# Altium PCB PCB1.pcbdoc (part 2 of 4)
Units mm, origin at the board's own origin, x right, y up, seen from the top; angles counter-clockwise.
Board outline 96.27 x 122.17 mm, 6 copper layers (Top Layer, Inner1, Inner2, Inner3, Inner4, Bottom Layer); 169 components, 166 nets, 787 pads, 477 vias.
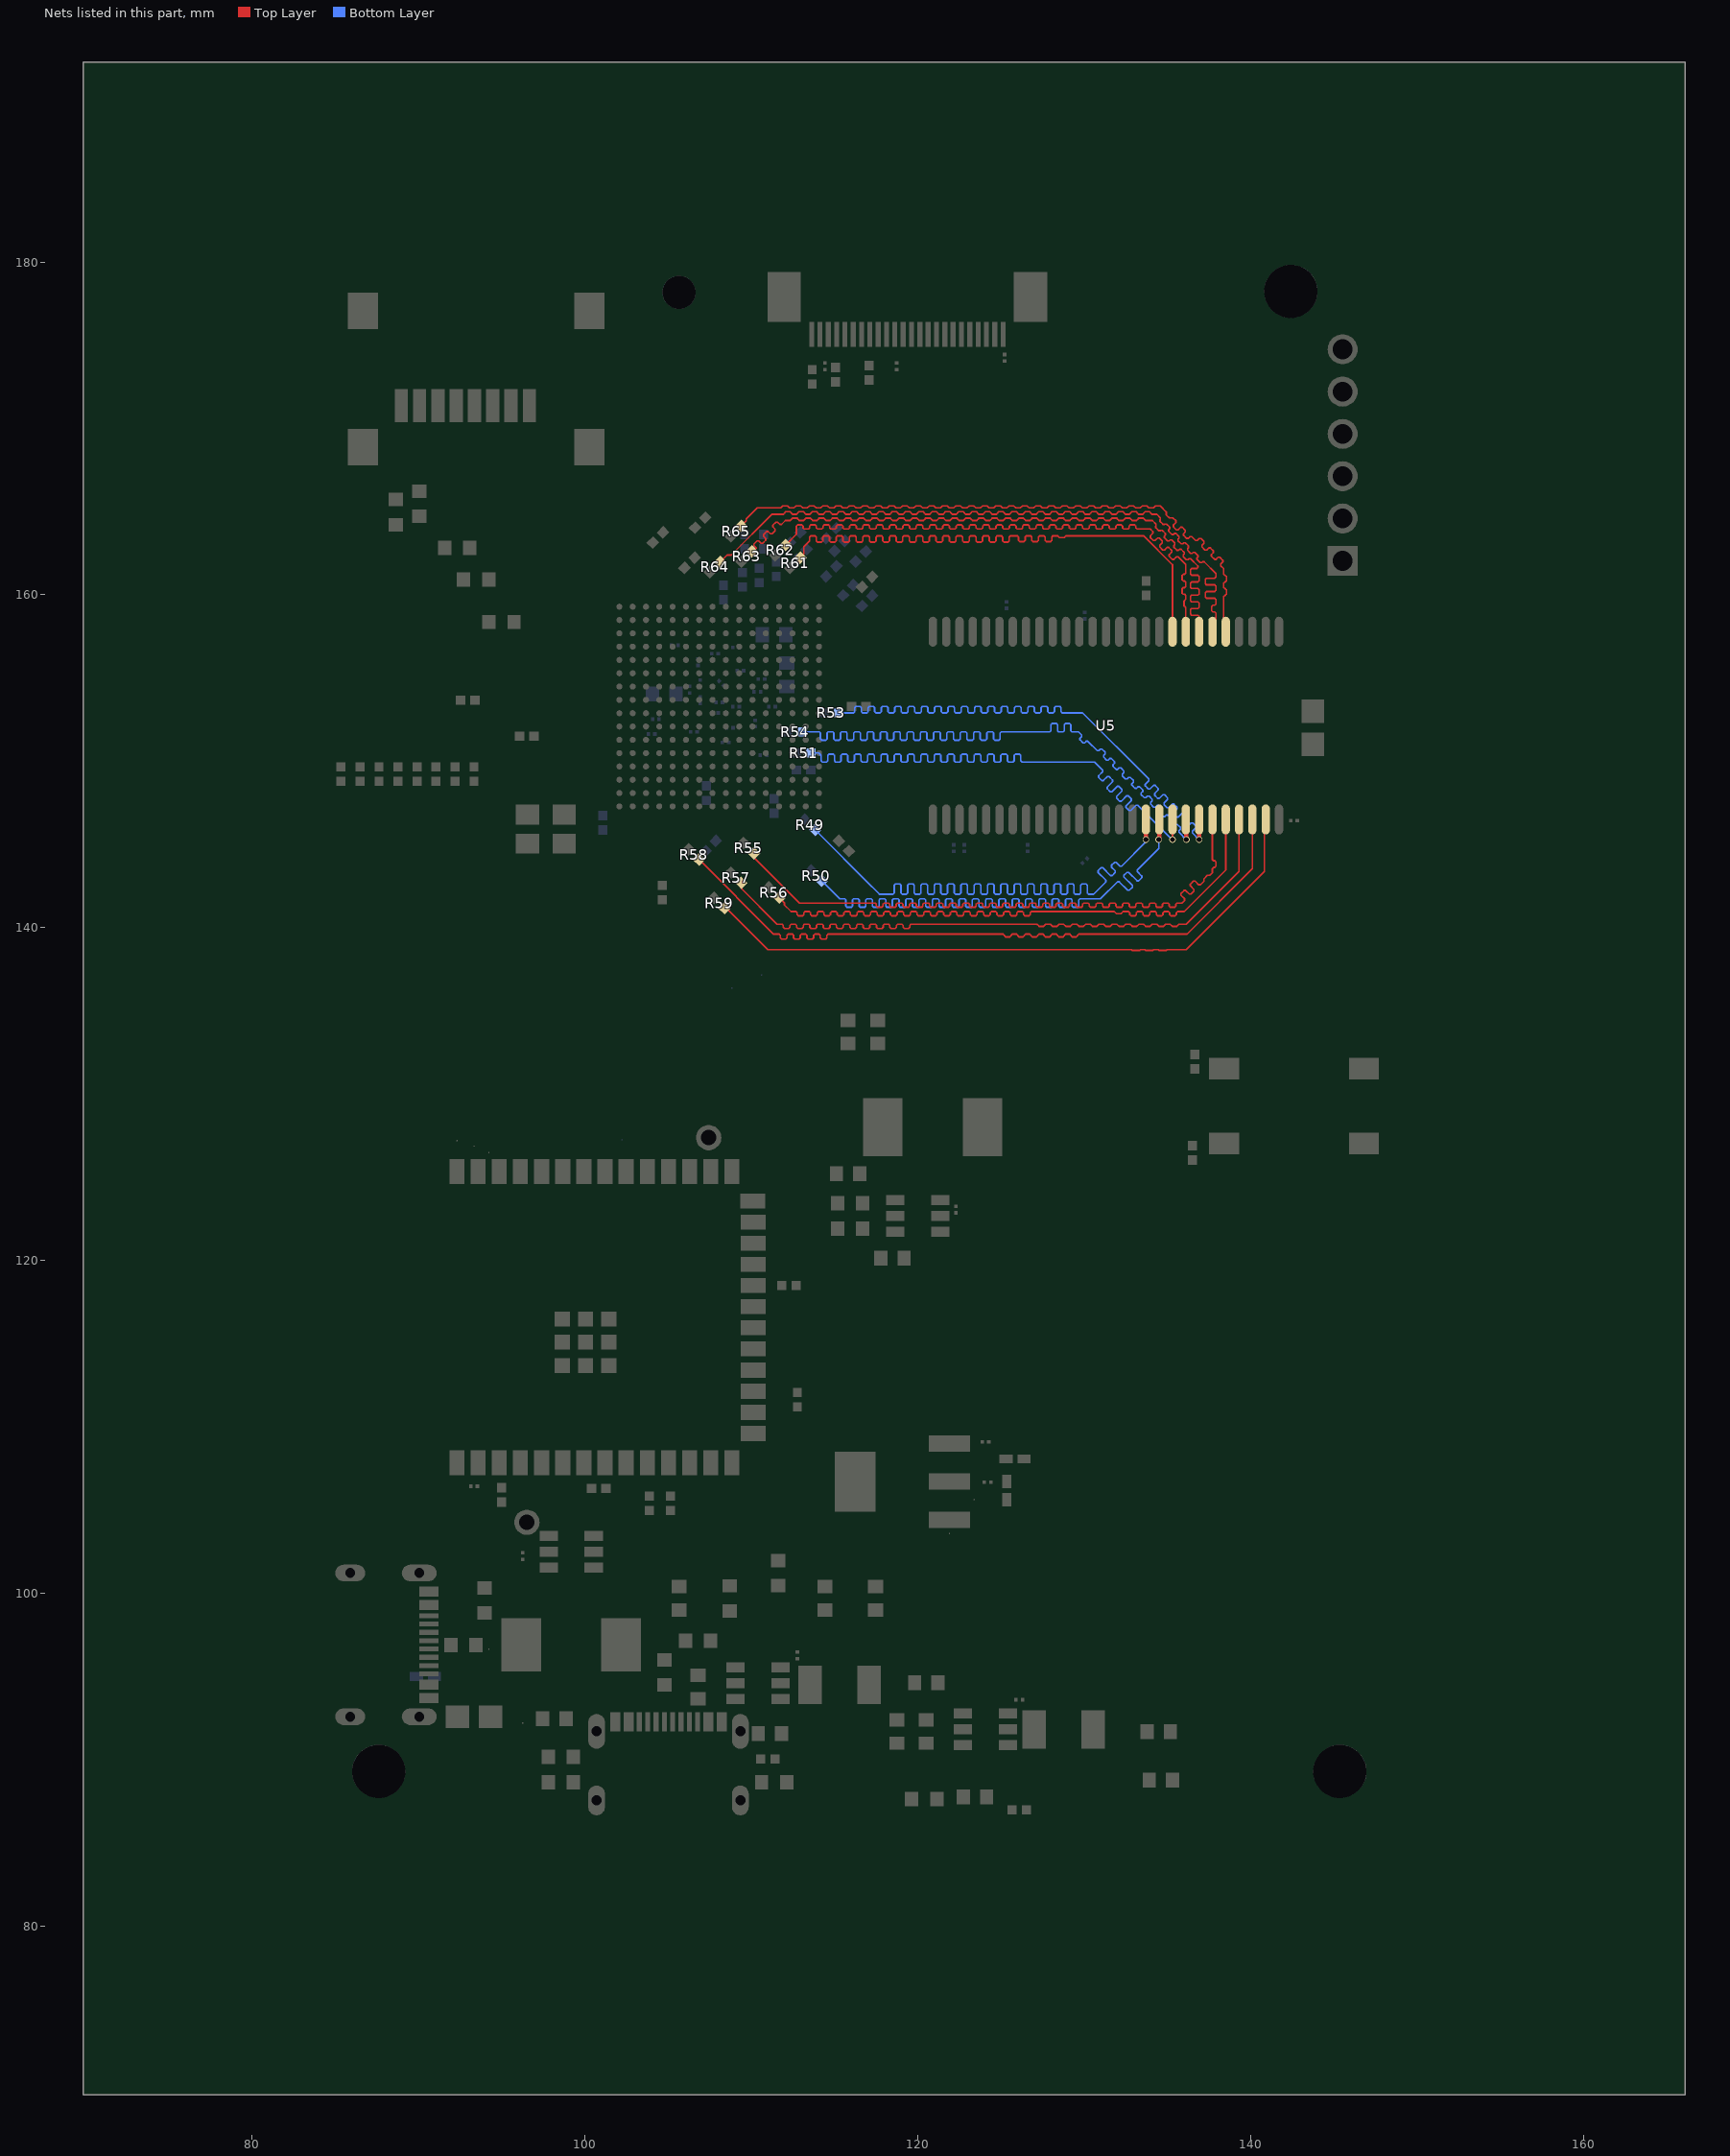
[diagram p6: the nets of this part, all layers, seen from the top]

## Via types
v1: diameter 0.4, hole 0.3, Top Layer to Bottom Layer, 448 vias
v2: diameter 1, hole 0.5, Top Layer to Bottom Layer, 28 vias
v3: diameter 0.5, hole 0.3, Top Layer to Bottom Layer, 1 vias

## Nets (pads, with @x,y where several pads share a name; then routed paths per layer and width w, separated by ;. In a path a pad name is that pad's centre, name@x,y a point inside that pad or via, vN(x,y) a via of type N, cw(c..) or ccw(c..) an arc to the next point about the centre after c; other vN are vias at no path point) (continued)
$1N71285: R49.2 U5.17 | length 42.2
  Top Layer w0.254: v1(133.718,145.288) U5.17@133.718,146.504
  Bottom Layer w0.1: R49.2@113.844,145.871 117.266,142.449 117.27,142.449 117.709,142.009 118.529,142.009 118.6,142.08 118.6,142.55 118.67,142.621 118.929,142.621 119,142.55 119,142.08 119.07,142.009 119.329,142.009 119.4,142.08 119.4,142.55 119.47,142.621 119.729,142.621 119.8,142.55 119.8,142.08 119.87,142.009 120.129,142.009 120.2,142.08 120.2,142.55 120.27,142.621 120.529,142.621 120.6,142.55 120.6,142.08 120.67,142.009 120.929,142.009 121,142.08 121,142.55 121.07,142.621 121.329,142.621 121.4,142.55 121.4,142.08 121.47,142.009 121.729,142.009 121.8,142.08 121.8,142.55 121.87,142.621 122.129,142.621 122.2,142.55 122.2,142.08 122.27,142.009 122.529,142.009 122.6,142.08 122.6,142.55 122.67,142.621 122.929,142.621 123,142.55 123,142.08 123.07,142.009 123.329,142.009 123.4,142.08 123.4,142.55 123.47,142.621 123.729,142.621 123.8,142.55 123.8,142.08 123.87,142.009 124.129,142.009 124.2,142.08 124.2,142.55 124.27,142.621 124.529,142.621 124.6,142.55 124.6,142.08 124.67,142.009 124.929,142.009 125,142.08 125,142.55 125.07,142.621 125.329,142.621 125.4,142.55 125.4,142.08 125.47,142.009 125.729,142.009 125.8,142.08 125.8,142.55 125.87,142.621 126.129,142.621 126.2,142.55 126.2,142.08 126.27,142.009 126.529,142.009 126.6,142.08 126.6,142.55 126.67,142.621 126.929,142.621 127,142.55 127,142.08 127.07,142.009 127.329,142.009 127.4,142.08 127.4,142.55 127.47,142.621 127.729,142.621 127.8,142.55 127.8,142.08 127.87,142.009 128.129,142.009 128.2,142.08 128.2,142.55 128.27,142.621 128.529,142.621 128.6,142.55 128.6,142.08 128.67,142.009 128.929,142.009 129,142.08 129,142.55 129.07,142.621 129.329,142.621 129.4,142.55 129.4,142.08 129.47,142.009 129.729,142.009 129.8,142.08 129.8,142.55 129.87,142.621 130.129,142.621 130.2,142.55 130.2,142.08 130.27,142.009 130.57,142.009 131.313,142.751 131.313,142.851 130.845,143.319 130.845,143.419 131.028,143.602 131.128,143.602 131.596,143.134 131.696,143.134 131.878,143.317 131.878,143.417 131.653,143.643 131.653,143.743 131.836,143.926 131.936,143.926 132.161,143.7 132.261,143.7 133.718,145.157 v1(133.718,145.288)
$1N71328: R50.2 U5.18 | length 41.7
  Top Layer w0.254: v1(134.493,145.288) 134.518,145.313 U5.18@134.518,146.504
  Bottom Layer w0.1: R50.2@114.225,142.823 115.316,141.732 115.616,141.732 115.687,141.661 115.687,141.295 115.757,141.224 116.016,141.224 116.087,141.295 116.087,141.661 116.157,141.732 116.416,141.732 116.487,141.661 116.487,141.295 116.557,141.224 116.816,141.224 116.887,141.295 116.887,141.661 116.957,141.732 117.216,141.732 117.287,141.661 117.287,141.295 117.357,141.224 117.616,141.224 117.687,141.295 117.687,141.661 117.757,141.732 118.016,141.732 118.087,141.661 118.087,141.295 118.157,141.224 118.416,141.224 118.487,141.295 118.487,141.661 118.557,141.732 118.816,141.732 118.887,141.661 118.887,141.295 118.957,141.224 119.216,141.224 119.287,141.295 119.287,141.661 119.357,141.732 119.616,141.732 119.687,141.661 119.687,141.295 119.757,141.224 120.016,141.224 120.087,141.295 120.087,141.661 120.157,141.732 120.416,141.732 120.487,141.661 120.487,141.295 120.557,141.224 120.816,141.224 120.887,141.295 120.887,141.661 120.957,141.732 121.216,141.732 121.287,141.661 121.287,141.295 121.357,141.224 121.616,141.224 121.687,141.295 121.687,141.661 121.757,141.732 122.016,141.732 122.087,141.661 122.087,141.295 122.157,141.224 122.416,141.224 122.487,141.295 122.487,141.661 122.557,141.732 122.816,141.732 122.887,141.661 122.887,141.295 122.957,141.224 123.216,141.224 123.287,141.295 123.287,141.661 123.357,141.732 123.616,141.732 123.687,141.661 123.687,141.295 123.757,141.224 124.016,141.224 124.087,141.295 124.087,141.661 124.157,141.732 124.416,141.732 124.487,141.661 124.487,141.295 124.557,141.224 124.816,141.224 124.887,141.295 124.887,141.661 124.957,141.732 125.216,141.732 125.287,141.661 125.287,141.295 125.357,141.224 125.616,141.224 125.687,141.295 125.687,141.661 125.757,141.732 126.016,141.732 126.087,141.661 126.087,141.295 126.157,141.224 126.416,141.224 126.487,141.295 126.487,141.661 126.557,141.732 126.816,141.732 126.887,141.661 126.887,141.295 126.957,141.224 127.216,141.224 127.287,141.295 127.287,141.661 127.357,141.732 127.616,141.732 127.687,141.661 127.687,141.295 127.757,141.224 128.016,141.224 128.087,141.295 128.087,141.661 128.157,141.732 128.416,141.732 128.487,141.661 128.487,141.295 128.557,141.224 128.816,141.224 128.887,141.295 128.887,141.661 128.957,141.732 129.216,141.732 129.287,141.661 129.287,141.295 129.357,141.224 129.616,141.224 129.687,141.295 129.687,141.661 129.757,141.732 130.985,141.732 132.014,142.761 132.114,142.761 132.625,142.25 132.725,142.25 132.908,142.433 132.908,142.533 132.397,143.044 132.397,143.144 132.579,143.327 132.679,143.327 133.191,142.816 133.291,142.816 133.473,142.998 133.473,143.098 133.199,143.373 133.199,143.473 134.493,144.768 v1(134.493,145.288)
$1N71371: R51.2 U5.19 | length 40.8
  Top Layer w0.1: v1(135.318,145.288) U5.19@135.318,146.504
  Bottom Layer w0.1: R51.2@113.59,150.495 114.064,150.495 114.2,150.358 114.2,150.029 114.271,149.958 114.53,149.958 114.6,150.029 114.6,150.358 114.671,150.429 114.93,150.429 115,150.358 115,150.029 115.071,149.958 115.33,149.958 115.4,150.029 115.4,150.358 115.471,150.429 115.73,150.429 115.8,150.358 115.8,150.029 115.871,149.958 116.13,149.958 116.2,150.029 116.2,150.358 116.271,150.429 116.53,150.429 116.6,150.358 116.6,150.029 116.671,149.958 116.93,149.958 117,150.029 117,150.358 117.071,150.429 117.33,150.429 117.4,150.358 117.4,150.029 117.471,149.958 117.73,149.958 117.8,150.029 117.8,150.358 117.871,150.429 118.13,150.429 118.2,150.358 118.2,150.029 118.271,149.958 118.53,149.958 118.6,150.029 118.6,150.358 118.671,150.429 118.93,150.429 119,150.358 119,150.029 119.071,149.958 119.33,149.958 119.4,150.029 119.4,150.358 119.471,150.429 119.73,150.429 119.8,150.358 119.8,150.029 119.871,149.958 120.13,149.958 120.2,150.029 120.2,150.358 120.271,150.429 120.53,150.429 120.6,150.358 120.6,150.029 120.671,149.958 120.93,149.958 121,150.029 121,150.358 121.071,150.429 121.33,150.429 121.4,150.358 121.4,150.029 121.471,149.958 121.73,149.958 121.8,150.029 121.8,150.358 121.871,150.429 122.13,150.429 122.2,150.358 122.2,150.029 122.271,149.958 122.53,149.958 122.6,150.029 122.6,150.358 122.671,150.429 122.93,150.429 123,150.358 123,150.029 123.071,149.958 123.33,149.958 123.4,150.029 123.4,150.358 123.471,150.429 123.73,150.429 123.8,150.358 123.8,150.029 123.871,149.958 124.13,149.958 124.2,150.029 124.2,150.358 124.271,150.429 124.53,150.429 124.6,150.358 124.6,150.029 124.671,149.958 124.93,149.958 125,150.029 125,150.358 125.071,150.429 125.33,150.429 125.4,150.358 125.4,150.029 125.471,149.958 125.73,149.958 125.8,150.029 125.8,150.358 125.871,150.429 126.13,150.429 126.2,150.358 126.2,150.029 126.271,149.958 130.627,149.958 131.119,149.466 131.119,149.366 130.881,149.127 130.881,149.027 131.064,148.844 131.164,148.844 131.402,149.083 131.502,149.083 131.714,148.871 131.714,148.771 131.395,148.453 131.395,148.353 131.578,148.17 131.678,148.17 131.997,148.489 132.097,148.489 132.28,148.306 132.28,148.206 131.961,147.887 131.961,147.787 132.144,147.604 132.244,147.604 132.563,147.923 132.663,147.923 132.845,147.74 132.845,147.64 132.527,147.321 132.527,147.221 132.71,147.039 132.81,147.039 133.128,147.357 133.228,147.357 135.17,145.415 135.191,145.415 v1(135.318,145.288)
$1N71457: R53.2 U5.21 | length 39.7
  Top Layer w0.254: v1(136.918,145.288) U5.21@136.918,146.504
  Bottom Layer w0.1: R53.2@115.241,152.908 116.151,152.908 116.222,152.979 116.222,153.218 116.293,153.289 116.551,153.289 116.622,153.218 116.622,152.979 116.693,152.908 116.951,152.908 117.022,152.979 117.022,153.218 117.093,153.289 117.351,153.289 117.422,153.218 117.422,152.979 117.493,152.908 117.751,152.908 117.822,152.979 117.822,153.218 117.893,153.289 118.151,153.289 118.222,153.218 118.222,152.979 118.293,152.908 118.551,152.908 118.622,152.979 118.622,153.218 118.693,153.289 118.951,153.289 119.022,153.218 119.022,152.979 119.093,152.908 119.351,152.908 119.422,152.979 119.422,153.218 119.493,153.289 119.751,153.289 119.822,153.218 119.822,152.979 119.893,152.908 120.151,152.908 120.222,152.979 120.222,153.218 120.293,153.289 120.551,153.289 120.622,153.218 120.622,152.979 120.693,152.908 120.951,152.908 121.022,152.979 121.022,153.218 121.093,153.289 121.351,153.289 121.422,153.218 121.422,152.979 121.493,152.908 121.751,152.908 121.822,152.979 121.822,153.218 121.893,153.289 122.151,153.289 122.222,153.218 122.222,152.979 122.293,152.908 122.551,152.908 122.622,152.979 122.622,153.218 122.693,153.289 122.951,153.289 123.022,153.218 123.022,152.979 123.093,152.908 123.351,152.908 123.422,152.979 123.422,153.218 123.493,153.289 123.751,153.289 123.822,153.218 123.822,152.979 123.893,152.908 124.151,152.908 124.222,152.979 124.222,153.218 124.293,153.289 124.551,153.289 124.622,153.218 124.622,152.979 124.693,152.908 124.951,152.908 125.022,152.979 125.022,153.218 125.093,153.289 125.351,153.289 125.422,153.218 125.422,152.979 125.493,152.908 125.751,152.908 125.822,152.979 125.822,153.218 125.893,153.289 126.151,153.289 126.222,153.218 126.222,152.979 126.293,152.908 126.551,152.908 126.622,152.979 126.622,153.218 126.693,153.289 126.951,153.289 127.022,153.218 127.022,152.979 127.093,152.908 127.351,152.908 127.422,152.979 127.422,153.218 127.493,153.289 127.751,153.289 127.822,153.218 127.822,152.979 127.893,152.908 128.151,152.908 128.222,152.979 128.222,153.218 128.293,153.289 128.551,153.289 128.622,153.218 128.622,152.979 128.693,152.908 129.921,152.908 133.892,148.937 133.892,148.837 133.68,148.626 133.68,148.526 133.863,148.343 133.963,148.343 134.175,148.554 134.275,148.554 134.458,148.371 134.458,148.271 134.246,148.06 134.246,147.96 134.429,147.777 134.529,147.777 134.74,147.989 134.84,147.989 135.023,147.806 135.023,147.706 134.812,147.494 134.812,147.394 134.995,147.211 135.095,147.211 135.306,147.423 135.406,147.423 135.589,147.24 135.589,147.14 135.377,146.929 135.377,146.829 135.56,146.646 135.66,146.646 135.872,146.857 135.972,146.857 136.155,146.674 136.155,146.574 135.943,146.363 135.943,146.263 136.126,146.08 136.226,146.08 136.437,146.292 136.537,146.292 136.72,146.109 136.72,146.009 136.509,145.797 136.509,145.697 v1(136.918,145.288)
$1N71500: R54.2 U5.20 | length 44
  Top Layer w0.254: U5.20@136.118,146.504 136.144,146.478 v1(136.144,145.288)
  Bottom Layer w0.1: R54.2@113.082,151.763 114.091,151.763 114.162,151.693 114.162,151.337 114.233,151.266 114.491,151.266 114.562,151.337 114.562,151.693 114.633,151.763 114.891,151.763 114.962,151.693 114.962,151.337 115.033,151.266 115.291,151.266 115.362,151.337 115.362,151.693 115.433,151.763 115.691,151.763 115.762,151.693 115.762,151.337 115.833,151.266 116.091,151.266 116.162,151.337 116.162,151.693 116.233,151.763 116.491,151.763 116.562,151.693 116.562,151.337 116.633,151.266 116.891,151.266 116.962,151.337 116.962,151.693 117.033,151.763 117.291,151.763 117.362,151.693 117.362,151.337 117.433,151.266 117.691,151.266 117.762,151.337 117.762,151.693 117.833,151.763 118.091,151.763 118.162,151.693 118.162,151.337 118.233,151.266 118.491,151.266 118.562,151.337 118.562,151.693 118.633,151.763 118.891,151.763 118.962,151.693 118.962,151.337 119.033,151.266 119.291,151.266 119.362,151.337 119.362,151.693 119.433,151.763 119.691,151.763 119.762,151.693 119.762,151.337 119.833,151.266 120.091,151.266 120.162,151.337 120.162,151.693 120.233,151.763 120.491,151.763 120.562,151.693 120.562,151.337 120.633,151.266 120.891,151.266 120.962,151.337 120.962,151.693 121.033,151.763 121.291,151.763 121.362,151.693 121.362,151.337 121.433,151.266 121.691,151.266 121.762,151.337 121.762,151.693 121.833,151.763 122.091,151.763 122.162,151.693 122.162,151.337 122.233,151.266 122.491,151.266 122.562,151.337 122.562,151.693 122.633,151.763 122.891,151.763 122.962,151.693 122.962,151.337 123.033,151.266 123.291,151.266 123.362,151.337 123.362,151.693 123.433,151.763 123.691,151.763 123.762,151.693 123.762,151.337 123.833,151.266 124.091,151.266 124.162,151.337 124.162,151.693 124.233,151.763 124.491,151.763 124.562,151.693 124.562,151.337 124.633,151.266 124.891,151.266 124.962,151.337 124.962,151.693 125.033,151.763 126.619,151.763 ; 126.671,151.763 127.94,151.763 128.01,151.834 128.01,152.202 128.081,152.273 128.34,152.273 128.41,152.202 128.41,151.834 128.481,151.763 128.74,151.763 128.81,151.834 128.81,152.202 128.881,152.273 129.14,152.273 129.21,152.202 129.21,151.834 129.281,151.763 129.669,151.763 129.85,151.582 129.85,151.482 129.759,151.392 129.759,151.292 129.942,151.109 130.042,151.109 130.132,151.2 130.232,151.2 130.793,150.639 130.893,150.639 130.983,150.73 131.083,150.73 131.266,150.547 131.266,150.447 131.176,150.356 131.176,150.256 131.358,150.074 131.458,150.074 131.549,150.164 131.649,150.164 131.832,149.981 131.832,149.881 131.741,149.791 131.741,149.691 131.924,149.508 132.024,149.508 132.115,149.598 132.215,149.598 132.397,149.416 132.397,149.316 132.307,149.225 132.307,149.125 132.49,148.942 132.59,148.942 132.68,149.033 132.78,149.033 132.963,148.85 132.963,148.75 132.873,148.659 132.873,148.559 133.055,148.377 133.155,148.377 133.246,148.467 133.346,148.467 133.529,148.284 133.529,148.184 133.438,148.094 133.438,147.994 133.621,147.811 133.721,147.811 133.812,147.901 133.912,147.901 134.095,147.718 134.095,147.618 134.004,147.528 134.004,147.428 134.187,147.245 134.287,147.245 134.377,147.336 134.477,147.336 134.66,147.153 134.66,147.053 134.57,146.962 134.57,146.862 134.753,146.679 134.853,146.679 134.943,146.77 135.043,146.77 135.226,146.587 135.226,146.487 135.135,146.397 135.135,146.297 135.318,146.114 135.418,146.114 135.509,146.204 135.609,146.204 135.792,146.021 135.792,145.921 135.701,145.831 135.701,145.731 v1(136.144,145.288)
$1N74645: R55.2 U5.22 | length 42.3
  Top Layer w0.1: R55.2@110.161,144.22 112.903,141.478 117.449,141.478 117.519,141.407 117.519,141.295 117.59,141.224 117.849,141.224 117.919,141.295 117.919,141.407 117.99,141.478 118.249,141.478 118.319,141.407 118.319,141.295 118.39,141.224 118.649,141.224 118.719,141.295 118.719,141.407 118.79,141.478 119.049,141.478 119.119,141.407 119.119,141.295 119.19,141.224 119.449,141.224 119.519,141.295 119.519,141.407 119.59,141.478 119.849,141.478 119.919,141.407 119.919,141.295 119.99,141.224 120.249,141.224 120.319,141.295 120.319,141.407 120.39,141.478 120.649,141.478 120.719,141.407 120.719,141.295 120.79,141.224 121.049,141.224 121.119,141.295 121.119,141.407 121.19,141.478 121.449,141.478 121.519,141.407 121.519,141.295 121.59,141.224 121.849,141.224 121.919,141.295 121.919,141.407 121.99,141.478 122.249,141.478 122.319,141.407 122.319,141.295 122.39,141.224 122.649,141.224 122.719,141.295 122.719,141.407 122.79,141.478 123.049,141.478 123.119,141.407 123.119,141.295 123.19,141.224 123.449,141.224 123.519,141.295 123.519,141.407 123.59,141.478 123.849,141.478 123.919,141.407 123.919,141.295 123.99,141.224 124.249,141.224 124.319,141.295 124.319,141.407 124.39,141.478 124.649,141.478 124.719,141.407 124.719,141.295 124.79,141.224 125.049,141.224 125.119,141.295 125.119,141.407 125.19,141.478 125.449,141.478 125.519,141.407 125.519,141.295 125.59,141.224 125.849,141.224 125.919,141.295 125.919,141.407 125.99,141.478 126.249,141.478 126.319,141.407 126.319,141.295 126.39,141.224 126.649,141.224 126.719,141.295 126.719,141.407 126.79,141.478 127.049,141.478 127.119,141.407 127.119,141.295 127.19,141.224 127.449,141.224 127.519,141.295 127.519,141.407 127.59,141.478 127.849,141.478 127.919,141.407 127.919,141.295 127.99,141.224 128.249,141.224 128.319,141.295 128.319,141.407 128.39,141.478 128.649,141.478 128.719,141.407 128.719,141.295 128.79,141.224 129.049,141.224 129.119,141.295 129.119,141.407 129.19,141.478 129.449,141.478 129.519,141.407 129.519,141.295 129.59,141.224 129.849,141.224 129.919,141.295 129.919,141.407 129.99,141.478 130.249,141.478 130.319,141.407 130.319,141.295 130.39,141.224 130.649,141.224 130.719,141.295 130.719,141.407 130.79,141.478 131.049,141.478 131.119,141.407 131.119,141.295 131.19,141.224 131.449,141.224 131.519,141.295 131.519,141.407 131.59,141.478 131.849,141.478 131.919,141.407 131.919,141.295 131.99,141.224 132.249,141.224 132.319,141.295 132.319,141.407 132.39,141.478 132.649,141.478 132.719,141.407 132.719,141.295 132.79,141.224 133.049,141.224 133.119,141.295 133.119,141.407 133.19,141.478 133.449,141.478 133.519,141.407 133.519,141.295 133.59,141.224 133.849,141.224 133.919,141.295 133.919,141.407 133.99,141.478 134.249,141.478 134.319,141.407 134.319,141.295 134.39,141.224 134.649,141.224 134.719,141.295 134.719,141.407 134.79,141.478 135.049,141.478 135.119,141.407 135.119,141.295 135.19,141.224 135.449,141.224 135.519,141.295 135.519,141.407 135.59,141.478 135.89,141.478 136.044,141.632 136.044,141.732 135.826,141.949 135.826,142.049 136.009,142.232 136.109,142.232 136.327,142.015 136.427,142.015 136.61,142.198 136.61,142.298 136.392,142.515 136.392,142.615 136.575,142.798 136.675,142.798 136.893,142.581 136.993,142.581 137.202,142.79 137.202,142.931 137.414,143.143 137.555,143.143 137.718,143.306 137.718,143.549 137.789,143.62 137.851,143.62 137.922,143.69 137.922,143.949 137.851,144.02 137.789,144.02 137.718,144.09 U5.22@137.718,146.504
$1N74688: R56.2 U5.23 | length 39
  Top Layer w0.1: R56.2@111.685,141.807 111.99,141.502 111.99,141.376 112.396,140.97 112.696,140.97 112.767,140.899 112.767,140.787 112.837,140.716 113.096,140.716 113.167,140.787 113.167,140.899 113.237,140.97 113.496,140.97 113.567,140.899 113.567,140.787 113.637,140.716 113.896,140.716 113.967,140.787 113.967,140.899 114.037,140.97 114.296,140.97 114.367,140.899 114.367,140.787 114.437,140.716 114.696,140.716 114.767,140.787 114.767,140.899 114.837,140.97 115.096,140.97 115.167,140.899 115.167,140.787 115.237,140.716 115.496,140.716 115.567,140.787 115.567,140.899 115.637,140.97 115.896,140.97 115.967,140.899 115.967,140.787 116.037,140.716 116.296,140.716 116.367,140.787 116.367,140.899 116.437,140.97 116.696,140.97 116.767,140.899 116.767,140.787 116.837,140.716 117.096,140.716 117.167,140.787 117.167,140.899 117.237,140.97 117.496,140.97 117.567,140.899 117.567,140.787 117.637,140.716 117.896,140.716 117.967,140.787 117.967,140.899 118.037,140.97 118.296,140.97 118.367,140.899 118.367,140.787 118.437,140.716 118.696,140.716 118.767,140.787 118.767,140.899 118.837,140.97 119.096,140.97 119.167,140.899 119.167,140.787 119.237,140.716 119.496,140.716 119.567,140.787 119.567,140.899 119.637,140.97 119.896,140.97 119.967,140.899 119.967,140.787 120.037,140.716 120.296,140.716 120.367,140.787 120.367,140.899 120.437,140.97 120.696,140.97 120.767,140.899 120.767,140.787 120.837,140.716 121.096,140.716 121.167,140.787 121.167,140.899 121.237,140.97 121.496,140.97 121.567,140.899 121.567,140.787 121.637,140.716 121.896,140.716 121.967,140.787 121.967,140.899 122.037,140.97 122.296,140.97 122.367,140.899 122.367,140.787 122.437,140.716 122.696,140.716 122.767,140.787 122.767,140.899 122.837,140.97 123.096,140.97 123.167,140.899 123.167,140.787 123.237,140.716 123.496,140.716 123.567,140.787 123.567,140.899 123.637,140.97 123.896,140.97 123.967,140.899 123.967,140.787 124.037,140.716 124.296,140.716 124.367,140.787 124.367,140.899 124.437,140.97 124.696,140.97 124.767,140.899 124.767,140.787 124.837,140.716 125.096,140.716 125.167,140.787 125.167,140.899 125.237,140.97 125.496,140.97 125.567,140.899 125.567,140.787 125.637,140.716 125.896,140.716 125.967,140.787 125.967,140.899 126.037,140.97 126.296,140.97 126.367,140.899 126.367,140.787 126.437,140.716 126.696,140.716 126.767,140.787 126.767,140.899 126.837,140.97 131.82,140.97 131.947,140.843 132.22,140.843 132.347,140.97 132.678,140.97 132.748,140.899 132.748,140.787 132.819,140.716 133.078,140.716 133.148,140.787 133.148,140.899 133.219,140.97 133.478,140.97 133.548,140.899 133.548,140.787 133.619,140.716 133.878,140.716 133.948,140.787 133.948,140.899 134.019,140.97 134.278,140.97 134.348,140.899 134.348,140.787 134.419,140.716 134.678,140.716 134.748,140.787 134.748,140.899 134.819,140.97 135.078,140.97 135.148,140.899 135.148,140.787 135.219,140.716 135.478,140.716 135.548,140.787 135.548,140.899 135.619,140.97 136.017,140.97 138.518,143.471 U5.23@138.518,146.504
$1N74731: R57.2 U5.24 | length 40.2
  Top Layer w0.1: R57.2@109.399,142.696 109.399,142.367 111.558,140.208 111.858,140.208 111.929,140.137 111.929,140.025 111.999,139.954 112.258,139.954 112.329,140.025 112.329,140.137 112.399,140.208 112.658,140.208 112.729,140.137 112.729,140.025 112.799,139.954 113.058,139.954 113.129,140.025 113.129,140.137 113.199,140.208 113.458,140.208 113.529,140.137 113.529,140.025 113.599,139.954 113.858,139.954 113.929,140.025 113.929,140.137 113.999,140.208 114.258,140.208 114.329,140.137 114.329,140.025 114.399,139.954 114.658,139.954 114.729,140.025 114.729,140.137 114.799,140.208 115.058,140.208 115.129,140.137 115.129,140.025 115.199,139.954 115.458,139.954 115.529,140.025 115.529,140.137 115.599,140.208 115.858,140.208 115.929,140.137 115.929,140.025 115.999,139.954 116.258,139.954 116.329,140.025 116.329,140.137 116.399,140.208 116.658,140.208 116.729,140.137 116.729,140.025 116.799,139.954 117.058,139.954 117.129,140.025 117.129,140.137 117.199,140.208 117.458,140.208 117.529,140.137 117.529,140.025 117.599,139.954 117.858,139.954 117.929,140.025 117.929,140.137 117.999,140.208 118.258,140.208 118.329,140.137 118.329,140.025 118.399,139.954 118.658,139.954 118.729,140.025 118.729,140.137 118.799,140.208 119.058,140.208 119.129,140.137 119.129,140.025 119.199,139.954 119.458,139.954 119.529,140.025 119.529,140.137 119.599,140.208 127.177,140.208 127.304,140.081 127.577,140.081 127.704,140.208 127.977,140.208 128.104,140.081 128.377,140.081 128.504,140.208 128.777,140.208 128.904,140.081 129.177,140.081 129.304,140.208 129.577,140.208 129.704,140.081 129.977,140.081 130.104,140.208 130.377,140.208 130.504,140.081 130.777,140.081 130.904,140.208 131.177,140.208 131.304,140.081 131.577,140.081 131.704,140.208 131.977,140.208 132.104,140.081 132.377,140.081 132.504,140.208 132.777,140.208 132.904,140.081 133.177,140.081 133.304,140.208 133.577,140.208 133.704,140.081 133.977,140.081 134.104,140.208 134.377,140.208 134.504,140.081 134.777,140.081 134.904,140.208 135.177,140.208 135.304,140.081 135.577,140.081 135.704,140.208 136.144,140.208 139.319,143.383 U5.24@139.319,146.503
$1N74774: R58.2 U5.25 | length 42.3
  Top Layer w0.1: R58.2@106.859,144.093 106.873,144.093 111.356,139.61 111.679,139.61 111.75,139.539 111.75,139.39 111.82,139.319 112.079,139.319 112.15,139.39 112.15,139.539 112.22,139.61 112.479,139.61 112.55,139.539 112.55,139.39 112.62,139.319 112.879,139.319 112.95,139.39 112.95,139.539 113.02,139.61 113.279,139.61 113.35,139.539 113.35,139.39 113.42,139.319 113.679,139.319 113.75,139.39 113.75,139.539 113.82,139.61 114.079,139.61 114.15,139.539 114.15,139.39 114.22,139.319 114.479,139.319 114.55,139.39 114.55,139.539 114.62,139.61 125.143,139.61 125.214,139.539 125.214,139.517 125.285,139.446 125.543,139.446 125.614,139.517 125.614,139.539 125.685,139.61 125.943,139.61 126.014,139.539 126.014,139.517 126.085,139.446 126.343,139.446 126.414,139.517 126.414,139.539 126.485,139.61 126.743,139.61 126.814,139.539 126.814,139.517 126.885,139.446 127.143,139.446 127.214,139.517 127.214,139.539 127.285,139.61 127.543,139.61 127.614,139.539 127.614,139.517 127.685,139.446 127.943,139.446 128.014,139.517 128.014,139.539 128.085,139.61 128.343,139.61 128.414,139.539 128.414,139.517 128.485,139.446 128.743,139.446 128.814,139.517 128.814,139.539 128.885,139.61 129.143,139.61 129.214,139.539 129.214,139.517 129.285,139.446 129.543,139.446 129.614,139.517 129.614,139.539 129.685,139.61 136.181,139.61 140.118,143.547 U5.25@140.118,146.504
$1N74817: R59.2 U5.26 | length 38.8
  Top Layer w0.1: R59.2@108.383,141.299 110.998,138.684 132.863,138.684 132.917,138.63 133.336,138.63 133.39,138.684 133.663,138.684 133.717,138.63 134.136,138.63 134.19,138.684 134.463,138.684 134.517,138.63 134.936,138.63 134.99,138.684 136.144,138.684 140.843,143.383 140.843,146.429 U5.26@140.918,146.504
$1N74931: R61.1 U5.36 | length 38.7
  Top Layer w0.1: R61.1@112.955,162.231 113.17,162.446 113.17,162.901 113.508,163.239 113.508,163.478 113.578,163.549 113.837,163.549 113.908,163.478 113.908,163.239 113.978,163.168 114.237,163.168 114.308,163.239 114.308,163.478 114.378,163.549 114.637,163.549 114.708,163.478 114.708,163.239 114.778,163.168 115.037,163.168 115.108,163.239 115.108,163.478 115.178,163.549 115.437,163.549 115.508,163.478 115.508,163.239 115.578,163.168 115.837,163.168 115.908,163.239 115.908,163.478 115.978,163.549 116.237,163.549 116.308,163.478 116.308,163.239 116.378,163.168 116.637,163.168 116.708,163.239 116.708,163.478 116.778,163.549 117.037,163.549 117.108,163.478 117.108,163.239 117.178,163.168 117.437,163.168 117.508,163.239 117.508,163.478 117.578,163.549 117.837,163.549 117.908,163.478 117.908,163.239 117.978,163.168 118.237,163.168 118.308,163.239 118.308,163.478 118.378,163.549 118.637,163.549 118.708,163.478 118.708,163.239 118.778,163.168 119.037,163.168 119.108,163.239 119.108,163.478 119.178,163.549 119.437,163.549 119.508,163.478 119.508,163.239 119.578,163.168 119.837,163.168 119.908,163.239 119.908,163.478 119.978,163.549 120.237,163.549 120.308,163.478 120.308,163.239 120.378,163.168 120.637,163.168 120.708,163.239 120.708,163.478 120.778,163.549 121.037,163.549 121.108,163.478 121.108,163.239 121.178,163.168 121.437,163.168 121.508,163.239 121.508,163.478 121.578,163.549 121.837,163.549 121.908,163.478 121.908,163.239 121.978,163.168 122.237,163.168 122.308,163.239 122.308,163.478 122.378,163.549 122.637,163.549 122.708,163.478 122.708,163.239 122.778,163.168 123.037,163.168 123.108,163.239 123.108,163.478 123.178,163.549 123.437,163.549 123.508,163.478 123.508,163.239 123.578,163.168 123.837,163.168 123.908,163.239 123.908,163.478 123.978,163.549 124.237,163.549 124.308,163.478 124.308,163.239 124.378,163.168 124.637,163.168 124.708,163.239 124.708,163.478 124.778,163.549 125.037,163.549 125.108,163.478 125.108,163.239 125.178,163.168 125.437,163.168 125.508,163.239 125.508,163.478 125.578,163.549 125.993,163.549 126.063,163.478 126.063,163.266 126.134,163.195 126.393,163.195 126.463,163.266 126.463,163.478 126.534,163.549 126.793,163.549 126.863,163.478 126.863,163.266 126.934,163.195 127.193,163.195 127.263,163.266 127.263,163.478 127.334,163.549 127.593,163.549 127.663,163.478 127.663,163.266 127.734,163.195 127.993,163.195 128.063,163.266 128.063,163.478 128.134,163.549 128.416,163.549 128.516,163.449 128.816,163.449 128.916,163.549 133.577,163.549 135.318,161.808 U5.36@135.318,157.788
$1N74974: R62.1 U5.35 | length 40.8
  Top Layer w0.1: R62.1@112.066,162.993 112.716,163.643 112.716,164.14 112.786,164.211 113.045,164.211 113.116,164.14 113.116,164.028 113.186,163.957 113.445,163.957 113.516,164.028 113.516,164.14 113.586,164.211 113.845,164.211 113.916,164.14 113.916,164.028 113.986,163.957 114.245,163.957 114.316,164.028 114.316,164.14 114.386,164.211 114.645,164.211 114.716,164.14 114.716,164.028 114.786,163.957 115.045,163.957 115.116,164.028 115.116,164.14 115.186,164.211 115.445,164.211 115.516,164.14 115.516,164.028 115.586,163.957 115.845,163.957 115.916,164.028 115.916,164.14 115.986,164.211 116.245,164.211 116.316,164.14 116.316,164.028 116.386,163.957 116.645,163.957 116.716,164.028 116.716,164.14 116.786,164.211 117.045,164.211 117.116,164.14 117.116,164.028 117.186,163.957 117.445,163.957 117.516,164.028 117.516,164.14 117.586,164.211 117.845,164.211 117.916,164.14 117.916,164.028 117.986,163.957 118.245,163.957 118.316,164.028 118.316,164.14 118.386,164.211 118.645,164.211 118.716,164.14 118.716,164.028 118.786,163.957 119.045,163.957 119.116,164.028 119.116,164.14 119.186,164.211 119.445,164.211 119.516,164.14 119.516,164.028 119.586,163.957 119.845,163.957 119.916,164.028 119.916,164.14 119.986,164.211 120.245,164.211 120.316,164.14 120.316,164.028 120.386,163.957 120.645,163.957 120.716,164.028 120.716,164.14 120.786,164.211 121.045,164.211 121.116,164.14 121.116,164.028 121.186,163.957 121.445,163.957 121.516,164.028 121.516,164.14 121.586,164.211 121.845,164.211 121.916,164.14 121.916,164.028 121.986,163.957 122.245,163.957 122.316,164.028 122.316,164.14 122.386,164.211 122.645,164.211 122.716,164.14 122.716,164.028 122.786,163.957 123.045,163.957 123.116,164.028 123.116,164.14 123.186,164.211 123.445,164.211 123.516,164.14 123.516,164.028 123.586,163.957 123.845,163.957 123.916,164.028 123.916,164.14 123.986,164.211 124.245,164.211 124.316,164.14 124.316,164.028 124.386,163.957 124.645,163.957 124.716,164.028 124.716,164.14 124.786,164.211 125.045,164.211 125.116,164.14 125.116,164.028 125.186,163.957 125.445,163.957 125.516,164.028 125.516,164.14 125.586,164.211 125.845,164.211 125.916,164.14 125.916,164.028 125.986,163.957 126.245,163.957 126.316,164.028 126.316,164.14 126.386,164.211 126.645,164.211 126.716,164.14 126.716,164.028 126.786,163.957 127.045,163.957 127.116,164.028 127.116,164.14 127.186,164.211 127.445,164.211 127.516,164.14 127.516,164.028 127.586,163.957 127.845,163.957 127.916,164.028 127.916,164.14 127.986,164.211 128.245,164.211 128.316,164.14 128.316,164.028 128.386,163.957 128.645,163.957 128.716,164.028 128.716,164.14 128.786,164.211 129.045,164.211 129.116,164.14 129.116,164.028 129.186,163.957 129.445,163.957 129.516,164.028 129.516,164.14 129.586,164.211 129.845,164.211 129.916,164.14 129.916,164.028 129.986,163.957 130.245,163.957 130.316,164.028 130.316,164.14 130.386,164.211 130.645,164.211 130.716,164.14 130.716,164.028 130.786,163.957 131.045,163.957 131.116,164.028 131.116,164.14 131.186,164.211 131.445,164.211 131.516,164.14 131.516,164.028 131.586,163.957 131.845,163.957 131.916,164.028 131.916,164.14 131.986,164.211 132.245,164.211 132.316,164.14 132.316,164.028 132.386,163.957 132.645,163.957 132.716,164.028 132.716,164.14 132.786,164.211 133.045,164.211 133.116,164.14 133.116,164.028 133.186,163.957 133.985,163.957 134.14,163.802 134.14,163.702 133.986,163.548 133.986,163.448 134.169,163.265 134.269,163.265 134.423,163.419 134.523,163.419 134.706,163.236 134.706,163.136 134.552,162.982 134.552,162.882 134.735,162.699 134.835,162.699 134.989,162.853 135.089,162.853 135.272,162.67 135.272,162.57 135.118,162.416 135.118,162.316 135.301,162.133 135.401,162.133 135.555,162.287 135.655,162.287 136.118,161.824 136.118,161.306 136.047,161.235 135.961,161.235 135.89,161.164 135.89,160.906 135.961,160.835 136.047,160.835 136.118,160.764 136.118,160.506 136.047,160.435 135.961,160.435 135.89,160.364 135.89,160.106 135.961,160.035 136.047,160.035 136.118,159.964 136.118,159.742 136.017,159.641 136.017,159.342 136.118,159.241 U5.35@136.118,157.788
$1N75017: R63.1 U5.34 | length 42.2
  Top Layer w0.1: R63.1@110.034,162.612 110.1,162.612 110.308,162.82 110.17,162.958 110.17,163.058 110.353,163.24 110.453,163.24 110.591,163.103 110.691,163.103 110.874,163.285 110.874,163.385 110.736,163.523 110.736,163.623 110.918,163.806 111.018,163.806 111.156,163.668 111.256,163.668 111.439,163.851 111.439,163.951 111.301,164.089 111.301,164.189 111.484,164.372 111.584,164.372 111.722,164.234 111.822,164.234 112.053,164.465 112.353,164.465 112.424,164.536 112.424,164.546 112.495,164.617 112.753,164.617 112.824,164.546 112.824,164.536 112.895,164.465 113.153,164.465 113.224,164.536 113.224,164.546 113.295,164.617 113.553,164.617 113.624,164.546 113.624,164.536 113.695,164.465 113.953,164.465 114.024,164.536 114.024,164.546 114.095,164.617 114.353,164.617 114.424,164.546 114.424,164.536 114.495,164.465 114.753,164.465 114.824,164.536 114.824,164.546 114.895,164.617 115.153,164.617 115.224,164.546 115.224,164.536 115.295,164.465 115.553,164.465 115.624,164.536 115.624,164.546 115.695,164.617 115.953,164.617 116.024,164.546 116.024,164.536 116.095,164.465 116.353,164.465 116.424,164.536 116.424,164.546 116.495,164.617 116.753,164.617 116.824,164.546 116.824,164.536 116.895,164.465 117.153,164.465 117.224,164.536 117.224,164.546 117.295,164.617 117.553,164.617 117.624,164.546 117.624,164.536 117.695,164.465 117.953,164.465 118.024,164.536 118.024,164.546 118.095,164.617 118.353,164.617 118.424,164.546 118.424,164.536 118.495,164.465 118.753,164.465 118.824,164.536 118.824,164.546 118.895,164.617 119.153,164.617 119.224,164.546 119.224,164.536 119.295,164.465 119.553,164.465 119.624,164.536 119.624,164.546 119.695,164.617 119.953,164.617 120.024,164.546 120.024,164.536 120.095,164.465 120.353,164.465 120.424,164.536 120.424,164.546 120.495,164.617 120.753,164.617 120.824,164.546 120.824,164.536 120.895,164.465 121.153,164.465 121.224,164.536 121.224,164.546 121.295,164.617 121.553,164.617 121.624,164.546 121.624,164.536 121.695,164.465 121.953,164.465 122.024,164.536 122.024,164.546 122.095,164.617 122.353,164.617 122.424,164.546 122.424,164.536 122.495,164.465 122.753,164.465 122.824,164.536 122.824,164.546 122.895,164.617 123.153,164.617 123.224,164.546 123.224,164.536 123.295,164.465 123.553,164.465 123.624,164.536 123.624,164.546 123.695,164.617 123.953,164.617 124.024,164.546 124.024,164.536 124.095,164.465 124.353,164.465 124.424,164.536 124.424,164.546 124.495,164.617 124.753,164.617 124.824,164.546 124.824,164.536 124.895,164.465 125.153,164.465 125.224,164.536 125.224,164.546 125.295,164.617 125.553,164.617 125.624,164.546 125.624,164.536 125.695,164.465 125.953,164.465 126.024,164.536 126.024,164.546 126.095,164.617 126.353,164.617 126.424,164.546 126.424,164.536 126.495,164.465 126.753,164.465 126.824,164.536 126.824,164.546 126.895,164.617 127.153,164.617 127.224,164.546 127.224,164.536 127.295,164.465 127.553,164.465 127.624,164.536 127.624,164.546 127.695,164.617 127.953,164.617 128.024,164.546 128.024,164.536 128.095,164.465 128.353,164.465 128.424,164.536 128.424,164.546 128.495,164.617 128.753,164.617 128.824,164.546 128.824,164.536 128.895,164.465 129.153,164.465 129.224,164.536 129.224,164.546 129.295,164.617 129.553,164.617 129.624,164.546 129.624,164.536 129.695,164.465 129.953,164.465 130.024,164.536 130.024,164.546 130.095,164.617 130.353,164.617 130.424,164.546 130.424,164.536 130.495,164.465 130.753,164.465 130.824,164.536 130.824,164.546 130.895,164.617 131.153,164.617 131.224,164.546 131.224,164.536 131.295,164.465 131.553,164.465 131.624,164.536 131.624,164.546 131.695,164.617 131.953,164.617 132.024,164.546 132.024,164.536 132.095,164.465 132.353,164.465 132.424,164.536 132.424,164.546 132.495,164.617 132.753,164.617 132.824,164.546 132.824,164.536 132.895,164.465 133.153,164.465 133.224,164.536 133.224,164.546 133.295,164.617 133.553,164.617 133.624,164.546 133.624,164.536 133.695,164.465 134.112,164.465 134.324,164.253 134.324,164.153 134.312,164.141 134.312,164.041 134.495,163.858 134.595,163.858 134.607,163.87 134.707,163.87 134.89,163.687 134.89,163.587 134.834,163.532 134.834,163.432 135.017,163.249 135.117,163.249 135.173,163.304 135.273,163.304 135.456,163.121 135.456,163.021 135.4,162.966 135.4,162.866 135.583,162.683 135.683,162.683 135.738,162.739 135.838,162.739 136.021,162.556 136.021,162.456 135.966,162.4 135.966,162.3 136.149,162.118 136.249,162.118 136.304,162.173 136.404,162.173 136.847,161.73 136.847,161.651 136.777,161.58 136.469,161.58 136.398,161.51 136.398,161.251 136.469,161.18 136.847,161.18 136.918,161.11 136.918,160.851 136.847,160.78 136.469,160.78 136.398,160.71 136.398,160.451 136.469,160.38 136.847,160.38 136.918,160.31 136.918,160.051 136.847,159.98 136.469,159.98 136.398,159.91 136.398,159.651 136.469,159.58 136.847,159.58 136.918,159.51 136.918,159.251 136.847,159.18 136.469,159.18 136.398,159.11 136.398,158.851 136.469,158.78 136.847,158.78 136.918,158.71 U5.34@136.918,157.788
$1N75060: R64.1 U5.33 | length 43.7
  Top Layer w0.1: R64.1@108.129,161.977 108.544,162.392 108.798,162.392 111.252,164.846 111.934,164.846 112.005,164.917 112.005,164.927 112.075,164.998 112.334,164.998 112.405,164.927 112.405,164.917 112.475,164.846 112.734,164.846 112.805,164.917 112.805,164.927 112.875,164.998 113.134,164.998 113.205,164.927 113.205,164.917 113.275,164.846 113.534,164.846 113.605,164.917 113.605,164.927 113.675,164.998 113.934,164.998 114.005,164.927 114.005,164.917 114.075,164.846 114.334,164.846 114.405,164.917 114.405,164.927 114.475,164.998 114.734,164.998 114.805,164.927 114.805,164.917 114.875,164.846 115.134,164.846 115.205,164.917 115.205,164.927 115.275,164.998 115.534,164.998 115.605,164.927 115.605,164.917 115.675,164.846 115.934,164.846 116.005,164.917 116.005,164.927 116.075,164.998 116.334,164.998 116.405,164.927 116.405,164.917 116.475,164.846 116.734,164.846 116.805,164.917 116.805,164.927 116.875,164.998 117.134,164.998 117.205,164.927 117.205,164.917 117.275,164.846 117.534,164.846 117.605,164.917 117.605,164.927 117.675,164.998 117.934,164.998 118.005,164.927 118.005,164.917 118.075,164.846 118.334,164.846 118.405,164.917 118.405,164.927 118.475,164.998 118.734,164.998 118.805,164.927 118.805,164.917 118.875,164.846 119.134,164.846 119.205,164.917 119.205,164.927 119.275,164.998 119.534,164.998 119.605,164.927 119.605,164.917 119.675,164.846 119.934,164.846 120.005,164.917 120.005,164.927 120.075,164.998 120.334,164.998 120.405,164.927 120.405,164.917 120.475,164.846 120.734,164.846 120.805,164.917 120.805,164.927 120.875,164.998 121.134,164.998 121.205,164.927 121.205,164.917 121.275,164.846 121.534,164.846 121.605,164.917 121.605,164.927 121.675,164.998 121.934,164.998 122.005,164.927 122.005,164.917 122.075,164.846 122.334,164.846 122.405,164.917 122.405,164.927 122.475,164.998 122.734,164.998 122.805,164.927 122.805,164.917 122.875,164.846 123.134,164.846 123.205,164.917 123.205,164.927 123.275,164.998 123.534,164.998 123.605,164.927 123.605,164.917 123.675,164.846 123.934,164.846 124.005,164.917 124.005,164.927 124.075,164.998 124.334,164.998 124.405,164.927 124.405,164.917 124.475,164.846 124.734,164.846 124.805,164.917 124.805,164.927 124.875,164.998 125.134,164.998 125.205,164.927 125.205,164.917 125.275,164.846 125.534,164.846 125.605,164.917 125.605,164.927 125.675,164.998 125.934,164.998 126.005,164.927 126.005,164.917 126.075,164.846 126.334,164.846 126.405,164.917 126.405,164.927 126.475,164.998 126.734,164.998 126.805,164.927 126.805,164.917 126.875,164.846 127.134,164.846 127.205,164.917 127.205,164.927 127.275,164.998 127.534,164.998 127.605,164.927 127.605,164.917 127.675,164.846 127.934,164.846 128.005,164.917 128.005,164.927 128.075,164.998 128.334,164.998 128.405,164.927 128.405,164.917 128.475,164.846 128.734,164.846 128.805,164.917 128.805,164.927 128.875,164.998 129.134,164.998 129.205,164.927 129.205,164.917 129.275,164.846 129.534,164.846 129.605,164.917 129.605,164.927 129.675,164.998 129.934,164.998 130.005,164.927 130.005,164.917 130.075,164.846 130.334,164.846 130.405,164.917 130.405,164.927 130.475,164.998 130.734,164.998 130.805,164.927 130.805,164.917 130.875,164.846 131.134,164.846 131.205,164.917 131.205,164.927 131.275,164.998 131.534,164.998 131.605,164.927 131.605,164.917 131.675,164.846 131.934,164.846 132.005,164.917 132.005,164.927 132.075,164.998 132.334,164.998 132.405,164.927 132.405,164.917 132.475,164.846 132.734,164.846 132.805,164.917 132.805,164.927 132.875,164.998 133.134,164.998 133.205,164.927 133.205,164.917 133.275,164.846 133.534,164.846 133.605,164.917 133.605,164.927 133.675,164.998 133.934,164.998 134.005,164.927 134.005,164.917 134.075,164.846 134.366,164.846 134.578,164.634 134.578,164.534 134.566,164.522 134.566,164.422 134.749,164.239 134.849,164.239 134.861,164.251 134.961,164.251 135.144,164.068 135.144,163.968 135.088,163.913 135.088,163.813 135.271,163.63 135.371,163.63 135.427,163.685 135.527,163.685 135.71,163.502 135.71,163.402 135.654,163.347 135.654,163.247 135.837,163.064 135.937,163.064 135.992,163.12 136.092,163.12 136.275,162.937 136.275,162.837 136.22,162.781 136.22,162.681 136.403,162.499 136.503,162.499 136.558,162.554 136.658,162.554 136.841,162.371 136.841,162.271 136.794,162.225 136.794,162.125 136.977,161.942 137.077,161.942 137.124,161.988 137.224,161.988 137.922,161.29 137.922,161.069 137.851,160.998 137.358,160.998 137.287,160.927 137.287,160.669 137.358,160.598 137.851,160.598 137.922,160.527 137.922,160.269 137.851,160.198 137.358,160.198 137.287,160.127 137.287,159.869 137.358,159.798 137.851,159.798 137.922,159.727 137.922,159.444 137.851,159.373 137.739,159.373 137.668,159.302 137.668,159.044 137.739,158.973 137.851,158.973 137.922,158.902 137.922,157.992 U5.33@137.718,157.788
$1N75103: R65.1 U5.32 | length 40.7
  Top Layer w0.1: R65.1@109.399,164.136 109.706,164.443 109.706,164.57 110.363,165.227 111.775,165.227 111.902,165.354 112.175,165.354 112.302,165.227 112.575,165.227 112.702,165.354 112.975,165.354 113.102,165.227 113.375,165.227 113.502,165.354 113.775,165.354 113.902,165.227 114.175,165.227 114.302,165.354 114.575,165.354 114.702,165.227 114.975,165.227 115.102,165.354 115.375,165.354 115.502,165.227 115.775,165.227 115.902,165.354 116.175,165.354 116.302,165.227 116.575,165.227 116.702,165.354 116.975,165.354 117.102,165.227 117.375,165.227 117.502,165.354 117.775,165.354 117.902,165.227 118.175,165.227 118.302,165.354 118.575,165.354 118.702,165.227 118.975,165.227 119.102,165.354 119.375,165.354 119.502,165.227 119.775,165.227 119.902,165.354 120.175,165.354 120.302,165.227 120.575,165.227 120.702,165.354 120.975,165.354 121.102,165.227 121.375,165.227 121.502,165.354 121.775,165.354 121.902,165.227 122.175,165.227 122.302,165.354 122.575,165.354 122.702,165.227 122.975,165.227 123.102,165.354 123.375,165.354 123.502,165.227 123.775,165.227 123.902,165.354 124.175,165.354 124.302,165.227 124.575,165.227 124.702,165.354 124.975,165.354 125.102,165.227 125.375,165.227 125.502,165.354 125.775,165.354 125.902,165.227 126.175,165.227 126.302,165.354 126.575,165.354 126.702,165.227 126.975,165.227 127.102,165.354 127.375,165.354 127.502,165.227 127.775,165.227 127.902,165.354 128.175,165.354 128.302,165.227 128.575,165.227 128.702,165.354 128.975,165.354 129.102,165.227 129.375,165.227 129.502,165.354 129.775,165.354 129.902,165.227 130.175,165.227 130.302,165.354 130.575,165.354 130.702,165.227 130.975,165.227 131.102,165.354 131.375,165.354 131.502,165.227 131.775,165.227 131.902,165.354 132.175,165.354 132.302,165.227 132.575,165.227 132.702,165.354 132.975,165.354 133.102,165.227 133.375,165.227 133.502,165.354 133.775,165.354 133.902,165.227 134.175,165.227 134.302,165.354 134.575,165.354 134.947,164.982 134.947,164.803 135.13,164.62 135.23,164.62 135.242,164.632 135.342,164.632 135.525,164.449 135.525,164.349 135.371,164.195 135.371,164.095 135.553,163.912 135.653,163.912 135.808,164.066 135.908,164.066 136.091,163.883 136.091,163.783 135.985,163.678 135.985,163.578 136.168,163.395 136.268,163.395 136.373,163.501 136.473,163.501 136.707,163.267 136.807,163.267 136.926,163.386 137.026,163.386 137.208,163.203 137.208,163.103 137.09,162.984 137.09,162.884 137.272,162.702 137.372,162.702 137.491,162.82 137.591,162.82 137.774,162.638 137.774,162.538 137.655,162.419 137.655,162.319 137.838,162.136 137.938,162.136 138.057,162.255 138.157,162.255 138.34,162.072 138.34,161.972 138.221,161.853 138.221,161.753 138.391,161.583 138.391,161.243 138.462,161.172 138.486,161.172 138.557,161.101 138.557,160.843 138.486,160.772 138.462,160.772 138.391,160.701 138.391,160.443 138.462,160.372 138.486,160.372 138.557,160.301 138.557,160.043 138.486,159.972 138.462,159.972 138.391,159.901 138.391,157.915 U5.32@138.518,157.788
